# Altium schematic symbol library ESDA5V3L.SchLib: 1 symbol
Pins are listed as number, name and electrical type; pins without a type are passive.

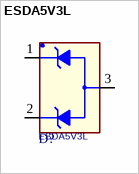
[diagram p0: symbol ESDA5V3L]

## ESDA5V3L
designator D?
footprint ST_SOT23-3L
pins: 1 K1, 2 K2, 3 A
